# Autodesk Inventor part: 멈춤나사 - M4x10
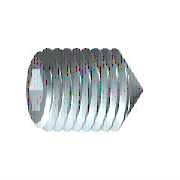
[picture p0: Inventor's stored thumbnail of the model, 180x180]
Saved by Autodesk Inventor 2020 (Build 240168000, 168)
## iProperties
Created: 2012-02
Part Number: 멈춤나사 - M4x10
Material: 강철, 연강
Description: 6각 소켓 머리 없는 멈춤 나사
Document SubType Name: Modeling
Standard: KS B 1028
Designer: mduedu
Standards Organization: KS
Language: ko-KR
Size Designation: 원추점 M4x10
Categories: <MemberInstance><Categories><Category DisplayName="조임쇠" InternalName="e4da775c-781d-43d5-af7c-5136215cf5a6" Mnemonic="FSTN"><Category DisplayName="볼트" InternalN
Density: 7.86 g/cm^3
Mass: 0.792069 g
Surface Area: 1.48192 cm^2
Volume: 0.100772 cm^3
Appearance: 강철
Author: mduedu
IsCustomPart: 1
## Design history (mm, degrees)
sketch "스케치1"
  geometry: L1 (0, 0)-(6.833, 0); L2 (10, 1.155)-(10, 2); L3 (10, 2)-(0, 2); L4 (10, 1.155)-(7.5, 1.155); L5 (7.5, 1.155)-(6.833, 0); L6 (0, -0.4)-(0, 2.4) reference; L7 (0, 2)-(0, 0)
  constraints: 13 end point, 3 parallel, 1 collinear, 1 perpendicular, 1 point on line
  dimensions: "d0" = 2.5 distance of L2.start L4.end (= INTI); "d1" = 60 deg angle of L5 L1; "d2" = 4 diameter of L3 L1 (= NND); "d3" = 2.3094 diameter of L4 L1 (= 1.1547 x SW); "d5" = 10 distance from line of L2 L3.end (= NLG)
revolve "본체" sketch "스케치1" stored, may be unused: angle "d6" = 90 deg
sketch "스케치2"
  geometry: L1 (-0.577, 1)-(0.577, 1); L2 (0.577, 1)-(1.155, 0); L3 (1.155, 0)-(0.577, -1); L4 (0.577, -1)-(-0.577, -1); L5 (-0.577, -1)-(-1.155, 0); L6 (-1.155, 0)-(-0.577, 1); 3 further points
  constraints: 12 end point, 1 coincident, 1 horizontal, 13 other
extrude "슬롯" join sketch "스케치2" taper "d7" = 0 deg; stored distance "d21" = 10
workaxis "Work Axis1"
workplane "Work Plane1"
sketch "스케치4"
  geometry: L1 (-5, 0.2)-(-3.2, 2) reference; L2 (-5, -0.2)-(-3.2, -2) reference; L3 (-3.2, 2)-(-5.2, 0); L4 (-3.2, -2)-(-5.2, 0); 2 further points
  constraints: 4 end point, 2 collinear, 1 coincident
body "Solid1"
feature "스레드" dims "d12" = 10 (= NLG), "d13" = 0
chamfer "모따기1" distance "d8" = 1.8 (computed from NND, SPD, FAWI); stored, may be unused: angle "d9" = 45 deg (= FAWI), second distance "d34" = 1.8 (computed from NND, SPD, FAWI)
chamfer "모따기2" distance "d10" = 0.42941 (= -0.5 x GD1 + 0.5 x NND); stored, may be unused: angle "d11" = 45 deg (= FAWI), second distance "d35" = 0.42941 (= -0.5 x GD1 + 0.5 x NND)
other parameters: "NND" = 4 [user parameter; used in 5 equation terms], "NLG" = 10 [user parameter; used in 2 equation terms], "INTI" = 2.5 [user parameter; used in 1 equation term], "FAWI" = 45 deg [user parameter; used in 4 equation terms], "SW" = 2 [user parameter; used in 2 equation terms], "GD1" = 3.14117 (= THREADDIA - 1.2269 x PTC) [user parameter; used in 2 equation terms], "d4" = 0, "FAWI1" = 45 deg [user parameter], "SPD" = 0.4 [user parameter; used in 2 equation terms], "d36" = 0, "d37" = 0, "GUL" = 0.42941 (= 0.61345 x PTC) [user parameter], "TPU" = 14.28571 (computed from PTC) [user parameter], "TOA" = 30 deg [user parameter], "THREADDIA" = 4 [user parameter; used in 1 equation term], "PTC" = 0.7 [user parameter; used in 4 equation terms], "GAL" = 0.42941 (= 0.61345 x PTC) [user parameter], "E0" = 2.31 (= 1.155 x SW) [user parameter]
